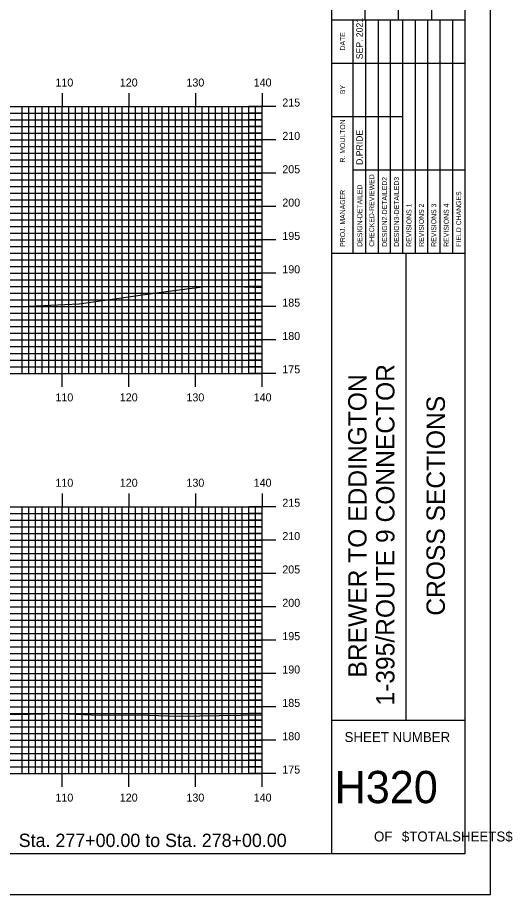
# Model space of a CAD drawing. Extents: x 1810193 to 1810536, y 442591 to 442811.
# Drawn here: x 1810462.2 to 1810536.4, y 442590.5 to 442722 of the extents above; entities that cross this region are included whole.
import ezdxf

# ---------------------------------------------------------------- set-up
doc = ezdxf.new("R2010")
doc.units = 0
for name, color, linetype in [('BORDER', 7, 'Continuous'), ('H_V ANNOTATION', 7, 'Continuous'), ('MAJOR', 7, 'Continuous'), ('MINOR', 7, 'Continuous'), ('PLOT BOUNDARY', 7, 'Continuous'), ('S_Roadway_Centerline', 7, 'Continuous')]:
    doc.layers.add(name, color=color, linetype=linetype)

msp = doc.modelspace()

# ---------------------------------------------------------------- linework, layer by layer
at = {"layer": 'BORDER'}
for p, q in [((1810509.26, 442596.67), (1810509.26, 442806.67)), ((1810514.26, 442721.67), (1810514.26, 442738.97)), ((1810519.26, 442721.67), (1810519.26, 442738.97)), ((1810524.26, 442721.67), (1810524.26, 442738.97)), ((1810509.26, 442721.67), (1810529.26, 442721.67)), ((1810509.26, 442686.67), (1810529.26, 442686.67)), ((1810520.45, 442616.67), (1810520.45, 442686.67)), ((1810509.26, 442616.67), (1810529.26, 442616.67))]:
    msp.add_line(p, q, dxfattribs=at)
msp.add_lwpolyline([(1810209.26, 442596.67), (1810529.26, 442596.67), (1810529.26, 442806.67), (1810209.26, 442806.67)], close=True, dxfattribs=at)
for points in [[(1810512.49, 442715.17), (1810512.49, 442721.67)], [(1810514.36, 442686.68), (1810514.36, 442721.67)], [(1810516.22, 442721.67), (1810516.22, 442686.68)], [(1810518.09, 442686.68), (1810518.09, 442721.67)], [(1810519.95, 442686.68), (1810519.95, 442721.67)], [(1810521.81, 442686.68), (1810521.81, 442721.67)], [(1810523.68, 442686.68), (1810523.68, 442721.67)], [(1810525.54, 442686.68), (1810525.54, 442721.67)], [(1810527.4, 442686.68), (1810527.4, 442721.67)], [(1810512.5, 442686.68), (1810512.5, 442720.26)], [(1810509.26, 442715.17), (1810529.26, 442715.17)], [(1810509.26, 442707.17), (1810512.5, 442707.17)], [(1810512.49, 442707.17), (1810519.95, 442707.17)], [(1810512.49, 442699.17), (1810529.26, 442699.17)]]:
    msp.add_lwpolyline(points, dxfattribs=at)
at = {"layer": 'MAJOR'}
for p, q in [((1810468.86, 442710.67), (1810468.86, 442708.67)), ((1810478.86, 442710.67), (1810478.86, 442708.67)), ((1810488.86, 442710.67), (1810488.86, 442708.67)), ((1810498.86, 442710.67), (1810498.86, 442708.67)), ((1810218.86, 442708.67), (1810498.86, 442708.67)), ((1810218.86, 442708.67), (1810498.86, 442708.67)), ((1810468.86, 442668.67), (1810468.86, 442708.67)), ((1810478.86, 442668.67), (1810478.86, 442708.67)), ((1810488.86, 442668.67), (1810488.86, 442708.67)), ((1810500.87, 442708.67), (1810496.86, 442708.67)), ((1810498.86, 442668.67), (1810498.86, 442708.67)), ((1810498.86, 442668.67), (1810498.86, 442708.67)), ((1810218.86, 442703.67), (1810498.86, 442703.67)), ((1810500.87, 442703.67), (1810496.86, 442703.67)), ((1810218.86, 442698.67), (1810498.86, 442698.67)), ((1810500.87, 442698.67), (1810496.86, 442698.67)), ((1810218.86, 442693.67), (1810498.86, 442693.67)), ((1810500.87, 442693.67), (1810496.86, 442693.67)), ((1810218.86, 442688.67), (1810498.86, 442688.67)), ((1810500.87, 442688.67), (1810496.86, 442688.67)), ((1810218.86, 442683.67), (1810498.86, 442683.67)), ((1810500.87, 442683.67), (1810496.86, 442683.67)), ((1810218.86, 442678.67), (1810498.86, 442678.67)), ((1810500.87, 442678.67), (1810496.86, 442678.67)), ((1810218.86, 442673.67), (1810498.86, 442673.67)), ((1810500.87, 442673.67), (1810496.86, 442673.67)), ((1810218.86, 442668.67), (1810498.86, 442668.67)), ((1810218.86, 442668.67), (1810498.86, 442668.67)), ((1810468.86, 442666.66), (1810468.86, 442668.67)), ((1810478.86, 442666.66), (1810478.86, 442668.67)), ((1810488.86, 442666.66), (1810488.86, 442668.67)), ((1810500.87, 442668.67), (1810496.86, 442668.67)), ((1810498.86, 442666.66), (1810498.86, 442668.67)), ((1810468.86, 442650.67), (1810468.86, 442648.67)), ((1810478.86, 442650.67), (1810478.86, 442648.67)), ((1810488.86, 442650.67), (1810488.86, 442648.67)), ((1810498.86, 442650.67), (1810498.86, 442648.67)), ((1810218.86, 442648.67), (1810498.86, 442648.67)), ((1810218.86, 442648.67), (1810498.86, 442648.67)), ((1810468.86, 442608.67), (1810468.86, 442648.67)), ((1810478.86, 442608.67), (1810478.86, 442648.67)), ((1810488.86, 442608.67), (1810488.86, 442648.67)), ((1810500.87, 442648.67), (1810496.86, 442648.67)), ((1810498.86, 442608.67), (1810498.86, 442648.67)), ((1810498.86, 442608.67), (1810498.86, 442648.67)), ((1810218.86, 442643.67), (1810498.86, 442643.67)), ((1810500.87, 442643.67), (1810496.86, 442643.67)), ((1810218.86, 442638.67), (1810498.86, 442638.67)), ((1810500.87, 442638.67), (1810496.86, 442638.67)), ((1810218.86, 442633.67), (1810498.86, 442633.67)), ((1810500.87, 442633.67), (1810496.86, 442633.67)), ((1810218.86, 442628.67), (1810498.86, 442628.67)), ((1810500.87, 442628.67), (1810496.86, 442628.67)), ((1810218.86, 442623.67), (1810498.86, 442623.67)), ((1810500.87, 442623.67), (1810496.86, 442623.67)), ((1810218.86, 442618.67), (1810498.86, 442618.67)), ((1810500.87, 442618.67), (1810496.86, 442618.67)), ((1810218.86, 442613.67), (1810498.86, 442613.67)), ((1810500.87, 442613.67), (1810496.86, 442613.67)), ((1810218.86, 442608.67), (1810498.86, 442608.67)), ((1810218.86, 442608.67), (1810498.86, 442608.67)), ((1810468.86, 442606.66), (1810468.86, 442608.67)), ((1810478.86, 442606.66), (1810478.86, 442608.67)), ((1810488.86, 442606.66), (1810488.86, 442608.67)), ((1810500.87, 442608.67), (1810496.86, 442608.67)), ((1810498.86, 442606.66), (1810498.86, 442608.67))]:
    msp.add_line(p, q, dxfattribs=at)
at = {"layer": 'MINOR'}
for p, q in [((1810462.86, 442668.67), (1810462.86, 442708.67)), ((1810463.86, 442668.67), (1810463.86, 442708.67)), ((1810464.86, 442668.67), (1810464.86, 442708.67)), ((1810465.86, 442668.67), (1810465.86, 442708.67)), ((1810466.86, 442668.67), (1810466.86, 442708.67)), ((1810467.86, 442668.67), (1810467.86, 442708.67)), ((1810469.86, 442668.67), (1810469.86, 442708.67)), ((1810470.86, 442668.67), (1810470.86, 442708.67)), ((1810471.86, 442668.67), (1810471.86, 442708.67)), ((1810472.86, 442668.67), (1810472.86, 442708.67)), ((1810473.86, 442668.67), (1810473.86, 442708.67)), ((1810474.86, 442668.67), (1810474.86, 442708.67)), ((1810475.86, 442668.67), (1810475.86, 442708.67)), ((1810476.86, 442668.67), (1810476.86, 442708.67)), ((1810477.86, 442668.67), (1810477.86, 442708.67)), ((1810479.86, 442668.67), (1810479.86, 442708.67)), ((1810480.86, 442668.67), (1810480.86, 442708.67)), ((1810481.86, 442668.67), (1810481.86, 442708.67)), ((1810482.86, 442668.67), (1810482.86, 442708.67)), ((1810483.86, 442668.67), (1810483.86, 442708.67)), ((1810484.86, 442668.67), (1810484.86, 442708.67)), ((1810485.86, 442668.67), (1810485.86, 442708.67)), ((1810486.86, 442668.67), (1810486.86, 442708.67)), ((1810487.86, 442668.67), (1810487.86, 442708.67)), ((1810489.86, 442668.67), (1810489.86, 442708.67)), ((1810490.86, 442668.67), (1810490.86, 442708.67)), ((1810491.86, 442668.67), (1810491.86, 442708.67)), ((1810492.86, 442668.67), (1810492.86, 442708.67)), ((1810493.86, 442668.67), (1810493.86, 442708.67)), ((1810494.86, 442668.67), (1810494.86, 442708.67)), ((1810495.86, 442668.67), (1810495.86, 442708.67)), ((1810496.86, 442668.67), (1810496.86, 442708.67)), ((1810497.86, 442668.67), (1810497.86, 442708.67)), ((1810218.86, 442707.67), (1810498.86, 442707.67)), ((1810498.86, 442707.67), (1810496.86, 442707.67)), ((1810218.86, 442706.67), (1810498.86, 442706.67)), ((1810218.86, 442705.67), (1810498.86, 442705.67)), ((1810498.86, 442706.67), (1810496.86, 442706.67)), ((1810498.86, 442705.67), (1810496.86, 442705.67)), ((1810218.86, 442704.67), (1810498.86, 442704.67)), ((1810498.86, 442704.67), (1810496.86, 442704.67)), ((1810218.86, 442702.67), (1810498.86, 442702.67)), ((1810218.86, 442701.67), (1810498.86, 442701.67)), ((1810498.86, 442702.67), (1810496.86, 442702.67)), ((1810498.86, 442701.67), (1810496.86, 442701.67)), ((1810218.86, 442700.67), (1810498.86, 442700.67)), ((1810498.86, 442700.67), (1810496.86, 442700.67)), ((1810218.86, 442699.67), (1810498.86, 442699.67)), ((1810498.86, 442699.67), (1810496.86, 442699.67)), ((1810218.86, 442697.67), (1810498.86, 442697.67)), ((1810498.86, 442697.67), (1810496.86, 442697.67)), ((1810218.86, 442696.67), (1810498.86, 442696.67)), ((1810498.86, 442696.67), (1810496.86, 442696.67)), ((1810218.86, 442695.67), (1810498.86, 442695.67)), ((1810498.86, 442695.67), (1810496.86, 442695.67)), ((1810218.86, 442694.67), (1810498.86, 442694.67)), ((1810498.86, 442694.67), (1810496.86, 442694.67)), ((1810218.86, 442692.67), (1810498.86, 442692.67)), ((1810498.86, 442692.67), (1810496.86, 442692.67)), ((1810218.86, 442691.67), (1810498.86, 442691.67)), ((1810498.86, 442691.67), (1810496.86, 442691.67)), ((1810218.86, 442690.67), (1810498.86, 442690.67)), ((1810498.86, 442690.67), (1810496.86, 442690.67)), ((1810218.86, 442689.67), (1810498.86, 442689.67)), ((1810498.86, 442689.67), (1810496.86, 442689.67)), ((1810218.86, 442687.67), (1810498.86, 442687.67)), ((1810498.86, 442687.67), (1810496.86, 442687.67)), ((1810218.86, 442686.67), (1810498.86, 442686.67)), ((1810498.86, 442686.67), (1810496.86, 442686.67)), ((1810218.86, 442685.67), (1810498.86, 442685.67)), ((1810218.86, 442684.67), (1810498.86, 442684.67)), ((1810498.86, 442685.67), (1810496.86, 442685.67)), ((1810498.86, 442684.67), (1810496.86, 442684.67)), ((1810218.86, 442682.67), (1810498.86, 442682.67)), ((1810498.86, 442682.67), (1810496.86, 442682.67)), ((1810218.86, 442681.67), (1810498.86, 442681.67)), ((1810218.86, 442680.67), (1810498.86, 442680.67)), ((1810498.86, 442681.67), (1810496.86, 442681.67)), ((1810498.86, 442680.67), (1810496.86, 442680.67)), ((1810218.86, 442679.67), (1810498.86, 442679.67)), ((1810498.86, 442679.67), (1810496.86, 442679.67)), ((1810218.86, 442677.67), (1810498.86, 442677.67)), ((1810218.86, 442676.67), (1810498.86, 442676.67)), ((1810498.86, 442677.67), (1810496.86, 442677.67)), ((1810498.86, 442676.67), (1810496.86, 442676.67)), ((1810218.86, 442675.67), (1810498.86, 442675.67)), ((1810498.86, 442675.67), (1810496.86, 442675.67)), ((1810218.86, 442674.67), (1810498.86, 442674.67)), ((1810498.86, 442674.67), (1810496.86, 442674.67)), ((1810218.86, 442672.67), (1810498.86, 442672.67)), ((1810498.86, 442672.67), (1810496.86, 442672.67)), ((1810218.86, 442671.67), (1810498.86, 442671.67)), ((1810498.86, 442671.67), (1810496.86, 442671.67)), ((1810218.86, 442670.67), (1810498.86, 442670.67)), ((1810498.86, 442670.67), (1810496.86, 442670.67)), ((1810218.86, 442669.67), (1810498.86, 442669.67)), ((1810498.86, 442669.67), (1810496.86, 442669.67)), ((1810218.86, 442647.67), (1810498.86, 442647.67)), ((1810462.86, 442608.67), (1810462.86, 442648.67)), ((1810463.86, 442608.67), (1810463.86, 442648.67)), ((1810464.86, 442608.67), (1810464.86, 442648.67)), ((1810465.86, 442608.67), (1810465.86, 442648.67)), ((1810466.86, 442608.67), (1810466.86, 442648.67)), ((1810467.86, 442608.67), (1810467.86, 442648.67)), ((1810469.86, 442608.67), (1810469.86, 442648.67)), ((1810470.86, 442608.67), (1810470.86, 442648.67)), ((1810471.86, 442608.67), (1810471.86, 442648.67)), ((1810472.86, 442608.67), (1810472.86, 442648.67)), ((1810473.86, 442608.67), (1810473.86, 442648.67)), ((1810474.86, 442608.67), (1810474.86, 442648.67)), ((1810475.86, 442608.67), (1810475.86, 442648.67)), ((1810476.86, 442608.67), (1810476.86, 442648.67)), ((1810477.86, 442608.67), (1810477.86, 442648.67)), ((1810479.86, 442608.67), (1810479.86, 442648.67)), ((1810480.86, 442608.67), (1810480.86, 442648.67)), ((1810481.86, 442608.67), (1810481.86, 442648.67)), ((1810482.86, 442608.67), (1810482.86, 442648.67)), ((1810483.86, 442608.67), (1810483.86, 442648.67)), ((1810484.86, 442608.67), (1810484.86, 442648.67)), ((1810485.86, 442608.67), (1810485.86, 442648.67)), ((1810486.86, 442608.67), (1810486.86, 442648.67)), ((1810487.86, 442608.67), (1810487.86, 442648.67)), ((1810489.86, 442608.67), (1810489.86, 442648.67)), ((1810490.86, 442608.67), (1810490.86, 442648.67)), ((1810491.86, 442608.67), (1810491.86, 442648.67)), ((1810492.86, 442608.67), (1810492.86, 442648.67)), ((1810493.86, 442608.67), (1810493.86, 442648.67)), ((1810494.86, 442608.67), (1810494.86, 442648.67)), ((1810495.86, 442608.67), (1810495.86, 442648.67)), ((1810496.86, 442608.67), (1810496.86, 442648.67)), ((1810498.86, 442647.67), (1810496.86, 442647.67)), ((1810497.86, 442608.67), (1810497.86, 442648.67)), ((1810218.86, 442646.67), (1810498.86, 442646.67)), ((1810498.86, 442646.67), (1810496.86, 442646.67)), ((1810218.86, 442645.67), (1810498.86, 442645.67)), ((1810498.86, 442645.67), (1810496.86, 442645.67)), ((1810218.86, 442644.67), (1810498.86, 442644.67)), ((1810498.86, 442644.67), (1810496.86, 442644.67)), ((1810218.86, 442642.67), (1810498.86, 442642.67)), ((1810498.86, 442642.67), (1810496.86, 442642.67)), ((1810218.86, 442641.67), (1810498.86, 442641.67)), ((1810498.86, 442641.67), (1810496.86, 442641.67)), ((1810218.86, 442640.67), (1810498.86, 442640.67)), ((1810498.86, 442640.67), (1810496.86, 442640.67)), ((1810218.86, 442639.67), (1810498.86, 442639.67)), ((1810498.86, 442639.67), (1810496.86, 442639.67)), ((1810218.86, 442637.67), (1810498.86, 442637.67)), ((1810498.86, 442637.67), (1810496.86, 442637.67)), ((1810218.86, 442636.67), (1810498.86, 442636.67)), ((1810498.86, 442636.67), (1810496.86, 442636.67)), ((1810218.86, 442635.67), (1810498.86, 442635.67)), ((1810218.86, 442634.67), (1810498.86, 442634.67)), ((1810498.86, 442635.67), (1810496.86, 442635.67)), ((1810498.86, 442634.67), (1810496.86, 442634.67)), ((1810218.86, 442632.67), (1810498.86, 442632.67)), ((1810498.86, 442632.67), (1810496.86, 442632.67)), ((1810218.86, 442631.67), (1810498.86, 442631.67)), ((1810218.86, 442630.67), (1810498.86, 442630.67)), ((1810498.86, 442631.67), (1810496.86, 442631.67)), ((1810498.86, 442630.67), (1810496.86, 442630.67)), ((1810218.86, 442629.67), (1810498.86, 442629.67)), ((1810498.86, 442629.67), (1810496.86, 442629.67)), ((1810218.86, 442627.67), (1810498.86, 442627.67)), ((1810218.86, 442626.67), (1810498.86, 442626.67)), ((1810498.86, 442627.67), (1810496.86, 442627.67)), ((1810498.86, 442626.67), (1810496.86, 442626.67)), ((1810218.86, 442625.67), (1810498.86, 442625.67)), ((1810498.86, 442625.67), (1810496.86, 442625.67)), ((1810218.86, 442624.67), (1810498.86, 442624.67)), ((1810498.86, 442624.67), (1810496.86, 442624.67)), ((1810218.86, 442622.67), (1810498.86, 442622.67)), ((1810498.86, 442622.67), (1810496.86, 442622.67)), ((1810218.86, 442621.67), (1810498.86, 442621.67)), ((1810498.86, 442621.67), (1810496.86, 442621.67)), ((1810218.86, 442620.67), (1810498.86, 442620.67)), ((1810498.86, 442620.67), (1810496.86, 442620.67)), ((1810218.86, 442619.67), (1810498.86, 442619.67)), ((1810498.86, 442619.67), (1810496.86, 442619.67)), ((1810218.86, 442617.67), (1810498.86, 442617.67)), ((1810498.86, 442617.67), (1810496.86, 442617.67)), ((1810218.86, 442616.67), (1810498.86, 442616.67)), ((1810498.86, 442616.67), (1810496.86, 442616.67)), ((1810218.86, 442615.67), (1810498.86, 442615.67)), ((1810498.86, 442615.67), (1810496.86, 442615.67)), ((1810218.86, 442614.67), (1810498.86, 442614.67)), ((1810498.86, 442614.67), (1810496.86, 442614.67)), ((1810218.86, 442612.67), (1810498.86, 442612.67)), ((1810498.86, 442612.67), (1810496.86, 442612.67)), ((1810218.86, 442611.67), (1810498.86, 442611.67)), ((1810498.86, 442611.67), (1810496.86, 442611.67)), ((1810218.86, 442610.67), (1810498.86, 442610.67)), ((1810218.86, 442609.67), (1810498.86, 442609.67)), ((1810498.86, 442610.67), (1810496.86, 442610.67)), ((1810498.86, 442609.67), (1810496.86, 442609.67))]:
    msp.add_line(p, q, dxfattribs=at)
at = {"layer": 'PLOT BOUNDARY'}
msp.add_lwpolyline([(1810193.08, 442590.55), (1810533.08, 442590.55), (1810533.08, 442810.55), (1810193.08, 442810.55)], close=True, dxfattribs=at)
at = {"layer": 'S_Roadway_Centerline'}
for points in [[(1810376.62, 442679.44), (1810394.66, 442679.11), (1810399.55, 442678.97), (1810408.54, 442678.88), (1810417.54, 442678.89), (1810420.74, 442678.92), (1810423.67, 442678.86), (1810432.55, 442678.64), (1810439.94, 442678.81), (1810449.02, 442678.82), (1810455.7, 442678.75), (1810462.8, 442678.71), (1810471.42, 442679.07), (1810484.46, 442680.92), (1810490.28, 442681.71), (1810496.17, 442681.64), (1810498.86, 442681.56)], [(1810380.51, 442618.21), (1810392.97, 442618.12), (1810398.64, 442618.08), (1810404.37, 442617.98), (1810410.19, 442617.74), (1810416.78, 442617.78), (1810428.61, 442617.8), (1810434.64, 442617.85), (1810439.35, 442617.9), (1810450.82, 442617.7), (1810461.79, 442617.52), (1810468.48, 442617.66), (1810474.48, 442617.44), (1810480.08, 442617.47), (1810486.51, 442617.28), (1810492.4, 442617.36), (1810498.86, 442617.49)]]:
    msp.add_lwpolyline(points, dxfattribs=at)

# ---------------------------------------------------------------- texts
at = {"layer": 'BORDER'}
for s, height, p in [('SEP. 2021', 0.969, (1810513.91, 442715.76)), ('DATE', 0.743, (1810511.27, 442717.08)), ('BY', 0.743, (1810511.27, 442710.54)), ('R. MOULTON', 0.745, (1810511.27, 442700.28)), ('D.PRIDE', 0.969, (1810513.91, 442699.92)), ('CHECKED-REVIEWED', 0.7455, (1810515.63, 442687.65)), ('DESIGN2-DETAILED2', 0.7455, (1810517.56, 442687.65)), ('DESIGN3-DETAILED3', 0.7455, (1810519.35, 442687.65)), ('DESIGN-DETAILED', 0.7455, (1810513.84, 442687.65)), ('PROJ. MANAGER', 0.7455, (1810511.27, 442687.65)), ('FIELD CHANGES', 0.7455, (1810528.67, 442687.65)), ('REVISIONS 1', 0.7455, (1810521.22, 442687.65)), ('REVISIONS 2', 0.7455, (1810523.08, 442687.65)), ('REVISIONS 3', 0.7455, (1810524.94, 442687.65)), ('REVISIONS 4', 0.7455, (1810526.81, 442687.65)), ('1-395/ROUTE 9 CONNECTOR', 2.7557, (1810518.67, 442618.87)), ('BREWER TO EDDINGTON', 2.7557, (1810514.49, 442623.07)), ('CROSS SECTIONS', 2.7557, (1810526.23, 442632.34))]:
    msp.add_text(s, height=height, rotation=90, dxfattribs=at).set_placement(p)
for s, height, p in [('SHEET NUMBER', 1.4905, (1810511.19, 442613.4)), ('H320', 4.839, (1810509.7, 442604.23)), ('OF', 1.491, (1810515.6, 442598.49)), ('$TOTALSHEETS$', 1.4905, (1810519.78, 442598.49))]:
    msp.add_text(s, height=height, dxfattribs=at).set_placement(p)
at = {"layer": 'H_V ANNOTATION'}
for s, height, p in [('110', 1.2, (1810467.85, 442711.67)), ('120', 1.2, (1810477.5, 442711.67)), ('130', 1.2, (1810487.49, 442711.67)), ('140', 1.2, (1810497.57, 442711.67)), ('215', 1.2, (1810501.86, 442708.67)), ('210', 1.2, (1810501.86, 442703.67)), ('205', 1.2, (1810501.86, 442698.67)), ('200', 1.2, (1810501.86, 442693.67)), ('195', 1.2, (1810501.86, 442688.67)), ('190', 1.2, (1810501.86, 442683.67)), ('185', 1.2, (1810501.86, 442678.67)), ('180', 1.2, (1810501.86, 442673.67)), ('175', 1.2, (1810501.86, 442668.67)), ('110', 1.2, (1810467.85, 442664.47)), ('120', 1.2, (1810477.5, 442664.47)), ('130', 1.2, (1810487.49, 442664.47)), ('140', 1.2, (1810497.57, 442664.47)), ('110', 1.2, (1810467.85, 442651.67)), ('120', 1.2, (1810477.5, 442651.67)), ('130', 1.2, (1810487.49, 442651.67)), ('140', 1.2, (1810497.57, 442651.67)), ('215', 1.2, (1810501.86, 442648.67)), ('210', 1.2, (1810501.86, 442643.67)), ('205', 1.2, (1810501.86, 442638.67)), ('200', 1.2, (1810501.86, 442633.67)), ('195', 1.2, (1810501.86, 442628.67)), ('190', 1.2, (1810501.86, 442623.67)), ('185', 1.2, (1810501.86, 442618.67)), ('180', 1.2, (1810501.86, 442613.67)), ('175', 1.2, (1810501.86, 442608.67)), ('110', 1.2, (1810467.85, 442604.47)), ('120', 1.2, (1810477.5, 442604.47)), ('130', 1.2, (1810487.49, 442604.47)), ('140', 1.2, (1810497.57, 442604.47)), ('Sta. 277+00.00 to Sta. 278+00.00', 2.0004, (1810462.35, 442597.66))]:
    msp.add_text(s, height=height, dxfattribs=at).set_placement(p)

doc.saveas('drawing.dxf')
